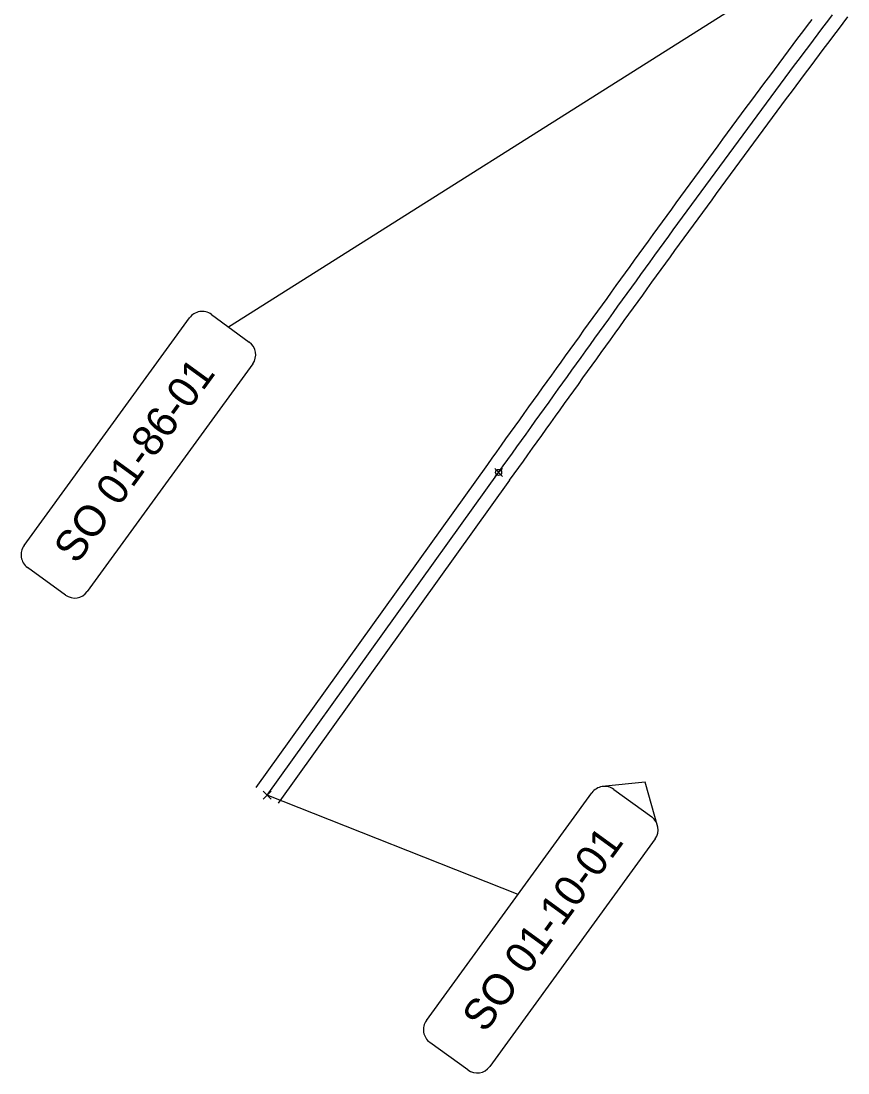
# Model space of a CAD drawing. Extents: x -541464 to -539952, y -1188799 to -1187382.
# Drawn here: x -541182 to -541077.9, y -1188519.2 to -1188386.8 of the extents above; entities that cross this region are included whole.
import ezdxf

# ---------------------------------------------------------------- set-up
doc = ezdxf.new("R2010")
doc.units = 0
doc.layers.add('SO 01-10-01', color=7, linetype='Continuous')
doc.layers.add('SO 01-86-01', color=7, linetype='Continuous')

msp = doc.modelspace()

# ---------------------------------------------------------------- linework, layer by layer
at = {"layer": 'SO 01-10-01'}
for p, q in [((-541083.007, -1188387.357), (-541082.41, -1188386.565)), ((-541081.053, -1188387.589), (-541080.457, -1188386.799)), ((-541080.457, -1188386.799), (-541079.859, -1188386.009)), ((-541078.504, -1188387.035), (-541077.907, -1188386.247)), ((-541083.603, -1188388.149), (-541083.007, -1188387.357)), ((-541081.649, -1188388.38), (-541081.053, -1188387.589)), ((-541079.696, -1188388.613), (-541079.1, -1188387.824)), ((-541079.1, -1188387.824), (-541078.504, -1188387.035)), ((-541084.794, -1188389.734), (-541084.199, -1188388.941)), ((-541084.199, -1188388.941), (-541083.603, -1188388.149)), ((-541082.84, -1188389.962), (-541082.245, -1188389.171)), ((-541082.245, -1188389.171), (-541081.649, -1188388.38)), ((-541080.886, -1188390.193), (-541080.292, -1188389.403)), ((-541080.292, -1188389.403), (-541079.696, -1188388.613)), ((-541085.983, -1188391.32), (-541085.389, -1188390.527)), ((-541085.389, -1188390.527), (-541084.794, -1188389.734)), ((-541084.028, -1188391.546), (-541083.434, -1188390.754)), ((-541083.434, -1188390.754), (-541082.84, -1188389.962)), ((-541081.481, -1188390.983), (-541080.886, -1188390.193)), ((-541086.576, -1188392.114), (-541085.983, -1188391.32)), ((-541084.622, -1188392.339), (-541084.028, -1188391.546)), ((-541082.668, -1188392.566), (-541082.074, -1188391.774)), ((-541082.074, -1188391.774), (-541081.481, -1188390.983)), ((-541087.762, -1188393.703), (-541087.169, -1188392.908)), ((-541087.169, -1188392.908), (-541086.576, -1188392.114)), ((-541085.807, -1188393.925), (-541085.215, -1188393.132)), ((-541085.215, -1188393.132), (-541084.622, -1188392.339)), ((-541083.853, -1188394.149), (-541083.261, -1188393.357)), ((-541083.261, -1188393.357), (-541082.668, -1188392.566)), ((-541088.946, -1188395.293), (-541088.354, -1188394.498)), ((-541088.354, -1188394.498), (-541087.762, -1188393.703)), ((-541086.99, -1188395.513), (-541086.399, -1188394.719)), ((-541086.399, -1188394.719), (-541085.807, -1188393.925)), ((-541084.445, -1188394.942), (-541083.853, -1188394.149)), ((-541089.537, -1188396.088), (-541088.946, -1188395.293)), ((-541087.581, -1188396.307), (-541086.99, -1188395.513)), ((-541085.627, -1188396.528), (-541085.036, -1188395.735)), ((-541085.036, -1188395.735), (-541084.445, -1188394.942)), ((-541090.718, -1188397.68), (-541090.127, -1188396.884)), ((-541090.127, -1188396.884), (-541089.537, -1188396.088)), ((-541088.762, -1188397.897), (-541088.172, -1188397.102)), ((-541088.172, -1188397.102), (-541087.581, -1188396.307)), ((-541086.807, -1188398.115), (-541086.217, -1188397.321)), ((-541086.217, -1188397.321), (-541085.627, -1188396.528)), ((-541091.896, -1188399.274), (-541091.307, -1188398.477)), ((-541091.307, -1188398.477), (-541090.718, -1188397.68)), ((-541089.941, -1188399.488), (-541089.351, -1188398.692)), ((-541089.351, -1188398.692), (-541088.762, -1188397.897)), ((-541087.396, -1188398.91), (-541086.807, -1188398.115)), ((-541092.485, -1188400.071), (-541091.896, -1188399.274)), ((-541090.529, -1188400.284), (-541089.941, -1188399.488)), ((-541088.574, -1188400.499), (-541087.985, -1188399.704)), ((-541087.985, -1188399.704), (-541087.396, -1188398.91)), ((-541093.662, -1188401.666), (-541093.074, -1188400.868)), ((-541093.074, -1188400.868), (-541092.485, -1188400.071)), ((-541091.705, -1188401.877), (-541091.118, -1188401.08)), ((-541091.118, -1188401.08), (-541090.529, -1188400.284)), ((-541089.75, -1188402.09), (-541089.162, -1188401.295)), ((-541089.162, -1188401.295), (-541088.574, -1188400.499)), ((-541094.836, -1188403.262), (-541094.249, -1188402.464)), ((-541094.249, -1188402.464), (-541093.662, -1188401.666)), ((-541092.88, -1188403.471), (-541092.293, -1188402.674)), ((-541092.293, -1188402.674), (-541091.705, -1188401.877)), ((-541090.337, -1188402.886), (-541089.75, -1188402.09)), ((-541095.423, -1188404.061), (-541094.836, -1188403.262)), ((-541093.467, -1188404.269), (-541092.88, -1188403.471)), ((-541091.511, -1188404.479), (-541090.924, -1188403.682)), ((-541090.924, -1188403.682), (-541090.337, -1188402.886)), ((-541096.595, -1188405.659), (-541096.009, -1188404.86)), ((-541096.009, -1188404.86), (-541095.423, -1188404.061)), ((-541094.639, -1188405.865), (-541094.053, -1188405.067)), ((-541094.053, -1188405.067), (-541093.467, -1188404.269)), ((-541092.683, -1188406.073), (-541092.097, -1188405.276)), ((-541092.097, -1188405.276), (-541091.511, -1188404.479)), ((-541097.766, -1188407.258), (-541097.181, -1188406.458)), ((-541097.181, -1188406.458), (-541096.595, -1188405.659)), ((-541095.809, -1188407.462), (-541095.224, -1188406.664)), ((-541095.224, -1188406.664), (-541094.639, -1188405.865)), ((-541093.268, -1188406.871), (-541092.683, -1188406.073)), ((-541098.351, -1188408.057), (-541097.766, -1188407.258)), ((-541096.394, -1188408.261), (-541095.809, -1188407.462)), ((-541094.438, -1188408.467), (-541093.853, -1188407.669)), ((-541093.853, -1188407.669), (-541093.268, -1188406.871)), ((-541099.52, -1188409.658), (-541098.935, -1188408.857)), ((-541098.935, -1188408.857), (-541098.351, -1188408.057)), ((-541097.562, -1188409.86), (-541096.978, -1188409.06)), ((-541096.978, -1188409.06), (-541096.394, -1188408.261)), ((-541095.606, -1188410.064), (-541095.022, -1188409.265)), ((-541095.022, -1188409.265), (-541094.438, -1188408.467)), ((-541100.687, -1188411.259), (-541100.103, -1188410.458)), ((-541100.103, -1188410.458), (-541099.52, -1188409.658)), ((-541098.146, -1188410.66), (-541097.562, -1188409.86)), ((-541096.19, -1188410.863), (-541095.606, -1188410.064)), ((-541101.27, -1188412.06), (-541100.687, -1188411.259)), ((-541099.313, -1188412.26), (-541098.73, -1188411.46)), ((-541098.73, -1188411.46), (-541098.146, -1188410.66)), ((-541097.356, -1188412.461), (-541096.773, -1188411.662)), ((-541096.773, -1188411.662), (-541096.19, -1188410.863)), ((-541102.435, -1188413.662), (-541101.853, -1188412.861)), ((-541101.853, -1188412.861), (-541101.27, -1188412.06)), ((-541100.478, -1188413.861), (-541099.895, -1188413.06)), ((-541099.895, -1188413.06), (-541099.313, -1188412.26)), ((-541098.521, -1188414.061), (-541097.939, -1188413.261)), ((-541097.939, -1188413.261), (-541097.356, -1188412.461)), ((-541103.599, -1188415.266), (-541103.018, -1188414.464)), ((-541103.018, -1188414.464), (-541102.435, -1188413.662)), ((-541101.06, -1188414.662), (-541100.478, -1188413.861)), ((-541099.103, -1188414.861), (-541098.521, -1188414.061)), ((-541104.181, -1188416.068), (-541103.599, -1188415.266)), ((-541102.224, -1188416.264), (-541101.642, -1188415.463)), ((-541101.642, -1188415.463), (-541101.06, -1188414.662)), ((-541100.266, -1188416.462), (-541099.685, -1188415.661)), ((-541099.685, -1188415.661), (-541099.103, -1188414.861)), ((-541105.344, -1188417.672), (-541104.763, -1188416.87)), ((-541104.763, -1188416.87), (-541104.181, -1188416.068)), ((-541103.386, -1188417.867), (-541102.805, -1188417.066)), ((-541102.805, -1188417.066), (-541102.224, -1188416.264)), ((-541101.429, -1188418.064), (-541100.848, -1188417.263)), ((-541100.848, -1188417.263), (-541100.266, -1188416.462)), ((-541106.505, -1188419.277), (-541105.924, -1188418.475)), ((-541105.924, -1188418.475), (-541105.344, -1188417.672)), ((-541103.967, -1188418.669), (-541103.386, -1188417.867)), ((-541102.009, -1188418.865), (-541101.429, -1188418.064)), ((-541107.085, -1188420.08), (-541106.505, -1188419.277)), ((-541105.128, -1188420.273), (-541104.547, -1188419.471)), ((-541104.547, -1188419.471), (-541103.967, -1188418.669)), ((-541103.17, -1188420.468), (-541102.59, -1188419.666)), ((-541102.59, -1188419.666), (-541102.009, -1188418.865)), ((-541108.245, -1188421.686), (-541107.666, -1188420.883)), ((-541107.666, -1188420.883), (-541107.085, -1188420.08)), ((-541106.287, -1188421.878), (-541105.708, -1188421.076)), ((-541105.708, -1188421.076), (-541105.128, -1188420.273)), ((-541103.75, -1188421.27), (-541103.17, -1188420.468)), ((-541109.405, -1188423.292), (-541108.825, -1188422.489)), ((-541108.825, -1188422.489), (-541108.245, -1188421.686)), ((-541106.867, -1188422.681), (-541106.287, -1188421.878)), ((-541104.909, -1188422.874), (-541104.33, -1188422.072)), ((-541104.33, -1188422.072), (-541103.75, -1188421.27)), ((-541109.984, -1188424.096), (-541109.405, -1188423.292)), ((-541108.026, -1188424.287), (-541107.447, -1188423.484)), ((-541107.447, -1188423.484), (-541106.867, -1188422.681)), ((-541106.068, -1188424.479), (-541105.489, -1188423.676)), ((-541105.489, -1188423.676), (-541104.909, -1188422.874)), ((-541111.142, -1188425.703), (-541110.563, -1188424.899)), ((-541110.563, -1188424.899), (-541109.984, -1188424.096)), ((-541109.184, -1188425.893), (-541108.605, -1188425.09)), ((-541108.605, -1188425.09), (-541108.026, -1188424.287)), ((-541106.647, -1188425.281), (-541106.068, -1188424.479)), ((-541112.299, -1188427.311), (-541111.721, -1188426.507)), ((-541111.721, -1188426.507), (-541111.142, -1188425.703)), ((-541109.762, -1188426.697), (-541109.184, -1188425.893)), ((-541107.804, -1188426.887), (-541107.226, -1188426.084)), ((-541107.226, -1188426.084), (-541106.647, -1188425.281)), ((-541112.877, -1188428.115), (-541112.299, -1188427.311)), ((-541110.919, -1188428.304), (-541110.341, -1188427.5)), ((-541110.341, -1188427.5), (-541109.762, -1188426.697)), ((-541108.961, -1188428.493), (-541108.383, -1188427.69)), ((-541108.383, -1188427.69), (-541107.804, -1188426.887)), ((-541114.034, -1188429.723), (-541113.456, -1188428.919)), ((-541113.456, -1188428.919), (-541112.877, -1188428.115)), ((-541112.075, -1188429.911), (-541111.497, -1188429.107)), ((-541111.497, -1188429.107), (-541110.919, -1188428.304)), ((-541109.539, -1188429.297), (-541108.961, -1188428.493)), ((-541114.612, -1188430.527), (-541114.034, -1188429.723)), ((-541112.653, -1188430.715), (-541112.075, -1188429.911)), ((-541110.695, -1188430.904), (-541110.117, -1188430.1)), ((-541110.117, -1188430.1), (-541109.539, -1188429.297)), ((-541115.767, -1188432.136), (-541115.189, -1188431.332)), ((-541115.189, -1188431.332), (-541114.612, -1188430.527)), ((-541113.809, -1188432.323), (-541113.231, -1188431.519)), ((-541113.231, -1188431.519), (-541112.653, -1188430.715)), ((-541111.85, -1188432.511), (-541111.273, -1188431.707)), ((-541111.273, -1188431.707), (-541110.695, -1188430.904)), ((-541116.922, -1188433.745), (-541116.345, -1188432.941)), ((-541116.345, -1188432.941), (-541115.767, -1188432.136)), ((-541114.964, -1188433.932), (-541114.386, -1188433.128)), ((-541114.386, -1188433.128), (-541113.809, -1188432.323)), ((-541112.428, -1188433.315), (-541111.85, -1188432.511)), ((-541117.5, -1188434.55), (-541116.922, -1188433.745)), ((-541115.541, -1188434.736), (-541114.964, -1188433.932)), ((-541113.583, -1188434.923), (-541113.005, -1188434.119)), ((-541113.005, -1188434.119), (-541112.428, -1188433.315)), ((-541118.654, -1188436.159), (-541118.077, -1188435.354)), ((-541118.077, -1188435.354), (-541117.5, -1188434.55)), ((-541116.695, -1188436.345), (-541116.118, -1188435.541)), ((-541116.118, -1188435.541), (-541115.541, -1188434.736)), ((-541114.737, -1188436.532), (-541114.16, -1188435.727)), ((-541114.16, -1188435.727), (-541113.583, -1188434.923)), ((-541119.808, -1188437.768), (-541119.231, -1188436.963)), ((-541119.231, -1188436.963), (-541118.654, -1188436.159)), ((-541117.273, -1188437.15), (-541116.695, -1188436.345)), ((-541115.314, -1188437.336), (-541114.737, -1188436.532)), ((-541120.385, -1188438.573), (-541119.808, -1188437.768)), ((-541118.427, -1188438.759), (-541117.85, -1188437.954)), ((-541117.85, -1188437.954), (-541117.273, -1188437.15)), ((-541116.468, -1188438.945), (-541115.891, -1188438.14)), ((-541115.891, -1188438.14), (-541115.314, -1188437.336)), ((-541121.539, -1188440.182), (-541120.962, -1188439.378)), ((-541120.962, -1188439.378), (-541120.385, -1188438.573)), ((-541119.58, -1188440.368), (-541119.004, -1188439.563)), ((-541119.004, -1188439.563), (-541118.427, -1188438.759)), ((-541117.622, -1188440.554), (-541117.045, -1188439.749)), ((-541117.045, -1188439.749), (-541116.468, -1188438.945)), ((-541122.693, -1188441.792), (-541122.116, -1188440.987)), ((-541122.116, -1188440.987), (-541121.539, -1188440.182)), ((-541120.157, -1188441.173), (-541119.58, -1188440.368)), ((-541118.199, -1188441.359), (-541117.622, -1188440.554)), ((-541123.269, -1188442.597), (-541122.693, -1188441.792)), ((-541121.311, -1188442.782), (-541120.734, -1188441.977)), ((-541120.734, -1188441.977), (-541120.157, -1188441.173)), ((-541119.352, -1188442.968), (-541118.776, -1188442.163)), ((-541118.776, -1188442.163), (-541118.199, -1188441.359)), ((-541152.399, -1188483.235), (-541123.269, -1188442.597)), ((-541151.017, -1188484.226), (-541121.888, -1188443.587)), ((-541122.388, -1188443.087), (-541121.388, -1188444.087)), ((-541121.388, -1188443.087), (-541122.388, -1188444.087)), ((-541121.888, -1188443.587), (-541121.311, -1188442.782)), ((-541119.929, -1188443.773), (-541119.352, -1188442.968)), ((-541120.506, -1188444.577), (-541149.635, -1188485.216)), ((-541120.506, -1188444.577), (-541119.929, -1188443.773)), ((-541103.445, -1188482.562), (-541108.859, -1188483.139)), ((-541101.83, -1188488.248), (-541103.445, -1188482.562)), ((-541151.517, -1188483.726), (-541150.517, -1188484.726)), ((-541150.517, -1188483.726), (-541151.517, -1188484.726)), ((-541119.436, -1188496.708), (-541151.017, -1188484.226)), ((-541130.979, -1188512.586), (-541110.144, -1188483.926)), ((-541107.394, -1188483.491), (-541102.617, -1188486.963)), ((-541102.182, -1188489.713), (-541123.017, -1188518.373)), ((-541125.767, -1188518.808), (-541130.544, -1188515.336))]:
    msp.add_line(p, q, dxfattribs=at)
msp.add_circle((-541121.888, -1188443.587), 0.375, dxfattribs=at)
for centre, start, end in [((-541108.552, -1188485.084), 53.98463, 143.98463), ((-541103.775, -1188488.556), 323.98463, 53.98463), ((-541129.387, -1188513.744), 143.98463, 233.98463), ((-541124.61, -1188517.216), 233.98463, 323.98463)]:
    msp.add_arc(centre, 1.969, start, end, dxfattribs=at)
at = {"layer": 'SO 01-86-01'}
for p, q in [((-541155.91, -1188425.271), (-541082.672, -1188379.02)), ((-541158.058, -1188423.709), (-541153.282, -1188427.182)), ((-541181.643, -1188452.804), (-541160.808, -1188424.144)), ((-541152.847, -1188429.931), (-541173.682, -1188458.592)), ((-541176.431, -1188459.027), (-541181.208, -1188455.554))]:
    msp.add_line(p, q, dxfattribs=at)
for centre, start, end in [((-541159.216, -1188425.302), 53.98463, 143.98463), ((-541154.44, -1188428.774), 323.98463, 53.98463), ((-541180.051, -1188453.962), 143.98463, 233.98463), ((-541175.274, -1188457.435), 233.98463, 323.98463)]:
    msp.add_arc(centre, 1.969, start, end, dxfattribs=at)

# ---------------------------------------------------------------- texts
at = {"layer": 'SO 01-10-01'}
msp.add_text('SO 01-10-01', height=3.9, rotation=53.98461, dxfattribs=at).set_placement((-541123.589, -1188514.258))
at = {"layer": 'SO 01-86-01'}
msp.add_text('SO 01-86-01', height=3.9, rotation=53.98461, dxfattribs=at).set_placement((-541175.006, -1188455.27))

doc.saveas('drawing.dxf')
